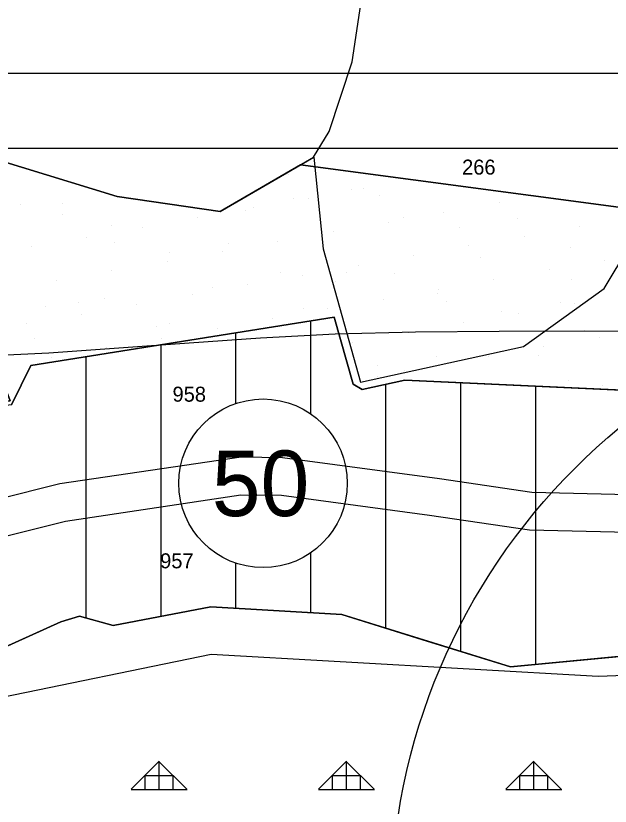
# Model space of a CAD drawing. Extents: x 410727 to 412947, y 4463506 to 4466382.
# Drawn here: x 411205.5 to 411364.1, y 4465781.8 to 4465992.7 of the extents above; entities that cross this region are included whole.
import ezdxf

# ---------------------------------------------------------------- set-up
doc = ezdxf.new("R2010")
doc.units = 0
for name, color, linetype in [('ADAKENARI', 7, 'Continuous'), ('KDS_PARSEL_NO', 7, 'Continuous'), ('KDS_PL', 7, 'Continuous'), ('LJ_ÇERÇEVE', 7, 'Continuous'), ('PL_AYA_ORMAN', 7, 'Continuous'), ('PL_AYA_PARK_DINLENME', 7, 'Continuous'), ('PL_KON_MEV_050', 7, 'Continuous'), ('PL_KON_ONE_50', 7, 'Continuous'), ('sembol', 7, 'Continuous'), ('TR_AZYOGUNLUK_MESKUN', 7, 'Continuous'), ('TR_GELİŞME_KONUT_ÇOKAZ', 7, 'Continuous'), ('TR_ORMAN', 7, 'Continuous'), ('TR_PARKALANI', 7, 'Continuous'), ('Yerlesime_uygunluk_sınırı', 7, 'Continuous')]:
    doc.layers.add(name, color=color, linetype=linetype)

msp = doc.modelspace()

# ---------------------------------------------------------------- linework, layer by layer
at = {"layer": 'ADAKENARI'}
for p, q in [((411209.5, 4465899.44), (411290.5, 4465912.31)), ((411290.5, 4465912.31), (411295.56, 4465894.44)), ((411204.34, 4465888.91), (411209.5, 4465899.44)), ((411295.56, 4465894.44), (411297.94, 4465893)), ((411297.94, 4465893), (411309.34, 4465895.53)), ((411309.34, 4465895.53), (411383, 4465892.12)), ((411231.5, 4465830), (411257.5, 4465834.97)), ((411257.5, 4465834.97), (411292.5, 4465832.97)), ((411188.5, 4465817.97), (411217.5, 4465830.97)), ((411217.5, 4465830.97), (411222.5, 4465832.5)), ((411222.5, 4465832.5), (411231.5, 4465830)), ((411292.5, 4465832.97), (411313.84, 4465826.33)), ((411313.84, 4465826.33), (411337.5, 4465818.97)), ((411337.5, 4465818.97), (411390, 4465824))]:
    msp.add_line(p, q, dxfattribs=at)
for points in [[(411041.23, 4465915.91), (411064.87, 4466022.46), (411117.76, 4466023.84), (411081.79, 4465955.55), (411117.13, 4465936.94), (411082.07, 4465924.54), (411082.97, 4465906.06), (411094.38, 4465893.75), (411095.5, 4465888.94), (411140, 4465889.38), (411204, 4465889.97), (411200.96, 4465897.85), (411190.46, 4465910.39), (411170, 4465921.75), (411155, 4465929), (411125.66, 4465939.96), (411143.96, 4465946.27), (411155.98, 4465967.98), (411178.81, 4465960.97), (411207.01, 4465952.32), (411232.5, 4465944.5), (411260, 4465940.47), (411281.5, 4465952.98), (411373.01, 4465940.76)], [(411373.01, 4465940.76), (411281.5, 4465952.98), (411260, 4465940.47), (411232.5, 4465944.5), (411207.01, 4465952.32), (411178.81, 4465960.97), (411155.98, 4465967.98), (411143.96, 4465946.27), (411125.66, 4465939.96), (411155, 4465929), (411170, 4465921.75), (411190.46, 4465910.39), (411200.96, 4465897.85), (411204, 4465889.97), (411140, 4465889.38), (411095.5, 4465888.94), (411094.38, 4465893.75), (411082.97, 4465906.06), (411082.07, 4465924.54), (411117.13, 4465936.94), (411081.79, 4465955.55), (411117.76, 4466023.84)], [(411383, 4465892.12), (411309.34, 4465895.53), (411297.94, 4465893), (411295.56, 4465894.44), (411290.5, 4465912.31), (411209.5, 4465899.44), (411204.34, 4465888.91)]]:
    msp.add_lwpolyline(points, dxfattribs=at)
at = {"layer": 'KDS_PL'}
for p, q in [((411295.29, 4465980.46), (411299.02, 4466005.3)), ((411289.1, 4465961.88), (411295.29, 4465980.46)), ((411284.98, 4465955), (411289.1, 4465961.88)), ((411178.81, 4465960.97), (411207.01, 4465952.32)), ((411260, 4465940.47), (411285, 4465955)), ((411260, 4465940.47), (411284.98, 4465955)), ((411285, 4465955), (411287.5, 4465930.5)), ((411207.01, 4465952.32), (411232.5, 4465944.5)), ((411232.5, 4465944.5), (411260, 4465940.47)), ((411232.5, 4465944.5), (411260, 4465940.47)), ((411362.5, 4465919.97), (411374.5, 4465940)), ((411287.5, 4465930.5), (411297.5, 4465895)), ((411341, 4465904.47), (411362.5, 4465919.97)), ((411209.5, 4465899.44), (411290.5, 4465912.31)), ((411290.5, 4465912.31), (411295.56, 4465894.44)), ((411297.5, 4465895), (411341, 4465904.47)), ((411204.34, 4465888.91), (411209.5, 4465899.44)), ((411295.56, 4465894.44), (411297.94, 4465893)), ((411297.94, 4465893), (411309.34, 4465895.53)), ((411309.34, 4465895.53), (411383, 4465892.12)), ((411265.62, 4465874.94), (411217.28, 4465867.81)), ((411276.66, 4465874.81), (411265.62, 4465874.94)), ((411318.62, 4465869.19), (411276.66, 4465874.81)), ((411343.25, 4465865.53), (411318.62, 4465869.19)), ((411217.28, 4465867.81), (411192.91, 4465861.72)), ((411218.75, 4465857.88), (411265.53, 4465864.91)), ((411265.53, 4465864.91), (411276.41, 4465864.84)), ((411276.41, 4465864.84), (411315.88, 4465859.44)), ((411401.38, 4465864.16), (411343.25, 4465865.53)), ((411315.88, 4465859.44), (411342.62, 4465855.53)), ((411196.06, 4465852.25), (411218.75, 4465857.88)), ((411342.62, 4465855.53), (411405.75, 4465854.06)), ((411257.5, 4465834.97), (411231.5, 4465830)), ((411292.5, 4465832.97), (411257.5, 4465834.97)), ((411217.5, 4465830.97), (411188.5, 4465817.97)), ((411222.5, 4465832.5), (411217.5, 4465830.97)), ((411231.5, 4465830), (411222.5, 4465832.5)), ((411337.5, 4465818.97), (411292.5, 4465832.97)), ((411390, 4465824), (411337.5, 4465818.97))]:
    msp.add_line(p, q, dxfattribs=at)
at = {"layer": 'LJ_ÇERÇEVE'}
msp.add_circle((411473.17, 4465753.45), 167.6, dxfattribs=at)
at = {"layer": 'PL_AYA_ORMAN'}
msp.add_lwpolyline([(411390, 4465824), (411337.5, 4465818.97), (411313.84, 4465826.33), (411292.5, 4465832.97), (411257.5, 4465834.97), (411231.5, 4465830), (411222.5, 4465832.5), (411217.5, 4465830.97), (411188.5, 4465817.97)], dxfattribs=at)
at = {"layer": 'PL_AYA_PARK_DINLENME'}
for points in [[(411373.01, 4465940.76), (411281.5, 4465952.98), (411260, 4465940.47), (411232.5, 4465944.5), (411207.01, 4465952.32), (411178.81, 4465960.97), (411155.98, 4465967.98), (411143.96, 4465946.27), (411125.66, 4465939.96), (411155, 4465929), (411170, 4465921.75), (411190.46, 4465910.39), (411200.96, 4465897.85), (411204, 4465889.97), (411140, 4465889.38), (411095.5, 4465888.94), (411094.38, 4465893.75), (411082.97, 4465906.06), (411082.07, 4465924.54), (411117.13, 4465936.94), (411081.79, 4465955.55), (411117.76, 4466023.84)], [(411204.34, 4465888.91), (411209.5, 4465899.44), (411290.5, 4465912.31), (411295.56, 4465894.44), (411297.94, 4465893), (411309.34, 4465895.53), (411383, 4465892.12)]]:
    msp.add_lwpolyline(points, dxfattribs=at)
at = {"layer": 'PL_KON_MEV_050'}
for points in [[(411383, 4465892.12), (411309.34, 4465895.53), (411297.94, 4465893), (411295.56, 4465894.44), (411290.5, 4465912.31), (411209.5, 4465899.44), (411204.34, 4465888.91), (411098.59, 4465875.88), (411099.72, 4465871.06), (411101.44, 4465857.22), (411112.42, 4465826.38), (411102.02, 4465825.57), (411084.31, 4465831.87), (411070.45, 4465837.6), (411056.58, 4465843.33), (411042.72, 4465849.06), (411028.86, 4465854.79), (411014.98, 4465860.52), (411001.12, 4465866.25), (410987.26, 4465871.98), (410978.34, 4465875.67), (410974.56, 4465876.98), (410957.12, 4465883.06)], [(411188.5, 4465817.97), (411217.5, 4465830.97), (411222.5, 4465832.5), (411231.5, 4465830), (411257.5, 4465834.97), (411292.5, 4465832.97), (411313.84, 4465826.33), (411337.5, 4465818.97), (411390, 4465824)]]:
    msp.add_lwpolyline(points, dxfattribs=at)
at = {"layer": 'PL_KON_ONE_50'}
msp.add_lwpolyline([(411081.79, 4465955.55), (411117.13, 4465936.94), (411082.07, 4465924.54), (411082.97, 4465906.06), (411094.38, 4465893.75), (411095.5, 4465888.94), (411140, 4465889.38), (411204, 4465889.97), (411200.96, 4465897.85), (411190.46, 4465910.39), (411170, 4465921.75), (411155, 4465929), (411125.66, 4465939.96), (411143.96, 4465946.27), (411155.98, 4465967.98), (411178.81, 4465960.97), (411207.01, 4465952.32), (411232.5, 4465944.5), (411260, 4465940.47), (411281.5, 4465952.98), (411373.01, 4465940.76)], dxfattribs=at)
at = {"layer": 'sembol'}
msp.add_circle((411271.47, 4465867.97), 22.5, dxfattribs=at)
at = {"layer": 'TR_AZYOGUNLUK_MESKUN'}
for p, q in [((411284.26, 4465886.49), (411284.26, 4465911.32)), ((411264.26, 4465889.29), (411264.26, 4465908.14)), ((411244.26, 4465832.44), (411244.26, 4465904.96)), ((411224.26, 4465832.01), (411224.26, 4465901.79)), ((411304.26, 4465829.31), (411304.26, 4465894.4)), ((411324.26, 4465823.09), (411324.26, 4465894.84)), ((411344.26, 4465819.62), (411344.26, 4465893.91)), ((411284.26, 4465833.44), (411284.26, 4465849.46)), ((411264.26, 4465834.58), (411264.26, 4465846.66))]:
    msp.add_line(p, q, dxfattribs=at)
at = {"layer": 'TR_GELİŞME_KONUT_ÇOKAZ'}
for p, q in [((411093.29, 4465977.39), (411432.99, 4465977.39)), ((411190.49, 4465957.39), (411455.67, 4465957.39))]:
    msp.add_line(p, q, dxfattribs=at)
msp.add_lwpolyline([(411191.27, 4466129.24), (411156.49, 4466097.39), (411117.76, 4466023.84), (411081.79, 4465955.55), (411117.13, 4465936.94), (411082.07, 4465924.54), (411082.97, 4465906.06), (411094.38, 4465893.75), (411095.5, 4465888.94), (411140, 4465889.38), (411204, 4465889.97), (411200.96, 4465897.85), (411190.46, 4465910.39), (411170, 4465921.75), (411155, 4465929), (411125.66, 4465939.96), (411143.96, 4465946.27), (411155.98, 4465967.98), (411178.81, 4465960.97), (411207.01, 4465952.32), (411232.5, 4465944.5), (411260, 4465940.47), (411281.5, 4465952.98), (411373.01, 4465940.76)], dxfattribs=at)
at = {"layer": 'TR_ORMAN'}
for p, q in [((411236.24, 4465786.35), (411243.74, 4465793.85)), ((411251.1, 4465786.34), (411243.6, 4465793.84)), ((411243.75, 4465786.29), (411243.75, 4465793.79)), ((411286.24, 4465786.36), (411293.74, 4465793.86)), ((411301.1, 4465786.34), (411293.6, 4465793.84)), ((411293.75, 4465786.29), (411293.75, 4465793.79)), ((411336.24, 4465786.37), (411343.74, 4465793.87)), ((411351.09, 4465786.34), (411343.59, 4465793.84)), ((411343.75, 4465786.29), (411343.75, 4465793.79)), ((411240, 4465790.04), (411247.5, 4465790.04)), ((411240, 4465786.29), (411240, 4465790.04)), ((411247.5, 4465786.29), (411247.5, 4465790.04)), ((411290, 4465790.04), (411297.5, 4465790.04)), ((411290, 4465786.29), (411290, 4465790.04)), ((411297.5, 4465786.29), (411297.5, 4465790.04)), ((411340, 4465790.04), (411347.5, 4465790.04)), ((411340, 4465786.29), (411340, 4465790.04)), ((411347.5, 4465786.29), (411347.5, 4465790.04)), ((411236.25, 4465786.29), (411251.25, 4465786.29)), ((411286.25, 4465786.29), (411301.25, 4465786.29)), ((411336.25, 4465786.29), (411351.25, 4465786.29))]:
    msp.add_line(p, q, dxfattribs=at)
at = {"layer": 'TR_PARKALANI'}
for p, q in [((411278.31, 4465950.38), (411278.31, 4465950.38)), ((411295.19, 4465946.35), (411295.19, 4465946.35)), ((411298.34, 4465946.67), (411298.34, 4465946.67)), ((411298.34, 4465946.67), (411298.34, 4465946.67)), ((411279.55, 4465944.03), (411279.55, 4465944.03)), ((411283.57, 4465944.07), (411283.57, 4465944.07)), ((411283.57, 4465944.07), (411283.57, 4465944.07)), ((411302.65, 4465944.7), (411302.65, 4465944.7)), ((411302.65, 4465944.7), (411302.65, 4465944.7)), ((411334.55, 4465942.9), (411334.55, 4465942.9)), ((411334.55, 4465942.9), (411334.55, 4465942.9)), ((411206.63, 4465942.46), (411206.63, 4465942.46)), ((411217.82, 4465942.63), (411217.82, 4465942.63)), ((411217.82, 4465942.63), (411217.82, 4465942.63)), ((411266.82, 4465940.74), (411266.82, 4465940.74)), ((411266.82, 4465940.74), (411266.82, 4465940.74)), ((411268.8, 4465941.46), (411268.8, 4465941.46)), ((411268.8, 4465941.46), (411268.8, 4465941.46)), ((411217.86, 4465939.68), (411217.86, 4465939.68)), ((411254.03, 4465938.86), (411254.03, 4465938.86)), ((411254.03, 4465938.86), (411254.03, 4465938.86)), ((411309.1, 4465938.82), (411309.1, 4465938.82)), ((411319.77, 4465940.3), (411319.77, 4465940.3)), ((411319.77, 4465940.3), (411319.77, 4465940.3)), ((411339.51, 4465938.54), (411339.51, 4465938.54)), ((411230.98, 4465936.78), (411230.98, 4465936.78)), ((411230.98, 4465936.78), (411230.98, 4465936.78)), ((411305, 4465937.69), (411305, 4465937.69)), ((411305, 4465937.69), (411305, 4465937.69)), ((411355.98, 4465936.53), (411355.98, 4465936.53)), ((411355.98, 4465936.53), (411355.98, 4465936.53)), ((411239.25, 4465936.25), (411239.25, 4465936.25)), ((411239.25, 4465936.25), (411239.25, 4465936.25)), ((411290.23, 4465935.09), (411290.23, 4465935.09)), ((411290.23, 4465935.09), (411290.23, 4465935.09)), ((411323.87, 4465936.22), (411323.87, 4465936.22)), ((411224.48, 4465933.65), (411224.48, 4465933.65)), ((411224.48, 4465933.65), (411224.48, 4465933.65)), ((411231.76, 4465932.15), (411231.76, 4465932.15)), ((411275.46, 4465932.48), (411275.46, 4465932.48)), ((411275.46, 4465932.48), (411275.46, 4465932.48)), ((411341.21, 4465933.92), (411341.21, 4465933.92)), ((411341.21, 4465933.92), (411341.21, 4465933.92)), ((411209.71, 4465931.04), (411209.71, 4465931.04)), ((411209.71, 4465931.04), (411209.71, 4465931.04)), ((411262.18, 4465931.87), (411262.18, 4465931.87)), ((411326.43, 4465931.32), (411326.43, 4465931.32)), ((411326.43, 4465931.32), (411326.43, 4465931.32)), ((411353.41, 4465931.01), (411353.41, 4465931.01)), ((411246.54, 4465929.55), (411246.54, 4465929.55)), ((411260.69, 4465929.88), (411260.69, 4465929.88)), ((411260.69, 4465929.88), (411260.69, 4465929.88)), ((411311.66, 4465928.71), (411311.66, 4465928.71)), ((411311.66, 4465928.71), (411311.66, 4465928.71)), ((411329.6, 4465928.15), (411329.6, 4465928.15)), ((411245.91, 4465927.27), (411245.91, 4465927.27)), ((411245.91, 4465927.27), (411245.91, 4465927.27)), ((411296.89, 4465926.11), (411296.89, 4465926.11)), ((411296.89, 4465926.11), (411296.89, 4465926.11)), ((411362.64, 4465927.55), (411362.64, 4465927.55)), ((411362.64, 4465927.55), (411362.64, 4465927.55)), ((411231.14, 4465924.67), (411231.14, 4465924.67)), ((411231.14, 4465924.67), (411231.14, 4465924.67)), ((411276.08, 4465924.34), (411276.08, 4465924.34)), ((411293.76, 4465924.19), (411293.76, 4465924.19)), ((411306.49, 4465924.05), (411306.49, 4465924.05)), ((411347.87, 4465924.94), (411347.87, 4465924.94)), ((411347.87, 4465924.94), (411347.87, 4465924.94)), ((411216.37, 4465922.06), (411216.37, 4465922.06)), ((411216.37, 4465922.06), (411216.37, 4465922.06)), ((411282.12, 4465923.5), (411282.12, 4465923.5)), ((411282.12, 4465923.5), (411282.12, 4465923.5)), ((411290.85, 4465921.73), (411290.85, 4465921.73)), ((411333.1, 4465922.34), (411333.1, 4465922.34)), ((411333.1, 4465922.34), (411333.1, 4465922.34)), ((411353.94, 4465922.47), (411353.94, 4465922.47)), ((411353.94, 4465922.47), (411353.94, 4465922.47)), ((411257.92, 4465920.22), (411257.92, 4465920.22)), ((411267.35, 4465920.9), (411267.35, 4465920.9)), ((411267.35, 4465920.9), (411267.35, 4465920.9)), ((411318.32, 4465919.73), (411318.32, 4465919.73)), ((411318.32, 4465919.73), (411318.32, 4465919.73)), ((411229.16, 4465917.38), (411229.16, 4465917.38)), ((411252.57, 4465918.29), (411252.57, 4465918.29)), ((411252.57, 4465918.29), (411252.57, 4465918.29)), ((411318.11, 4465918.51), (411318.11, 4465918.51)), ((411318.11, 4465918.51), (411318.11, 4465918.51)), ((411222.09, 4465916.26), (411222.09, 4465916.26)), ((411237.8, 4465915.69), (411237.8, 4465915.69)), ((411237.8, 4465915.69), (411237.8, 4465915.69)), ((411303.55, 4465917.13), (411303.55, 4465917.13)), ((411303.55, 4465917.13), (411303.55, 4465917.13)), ((411320.4, 4465916.52), (411320.4, 4465916.52)), ((411350.81, 4465916.24), (411350.81, 4465916.24)), ((411354.53, 4465915.96), (411354.53, 4465915.96)), ((411354.53, 4465915.96), (411354.53, 4465915.96)), ((411213.52, 4465915.06), (411213.52, 4465915.06)), ((411282.27, 4465914.54), (411282.27, 4465914.54)), ((411282.27, 4465914.54), (411282.27, 4465914.54)), ((411288.78, 4465914.52), (411288.78, 4465914.52)), ((411288.78, 4465914.52), (411288.78, 4465914.52)), ((411335.17, 4465913.92), (411335.17, 4465913.92)), ((411339.76, 4465913.36), (411339.76, 4465913.36)), ((411339.76, 4465913.36), (411339.76, 4465913.36)), ((411223.03, 4465913.08), (411223.03, 4465913.08)), ((411223.03, 4465913.08), (411223.03, 4465913.08)), ((411274.01, 4465911.92), (411274.01, 4465911.92)), ((411274.01, 4465911.92), (411274.01, 4465911.92)), ((411208.26, 4465910.48), (411208.26, 4465910.48)), ((411208.26, 4465910.48), (411208.26, 4465910.48)), ((411243.06, 4465909.85), (411243.06, 4465909.85)), ((411246.43, 4465910.58), (411246.43, 4465910.58)), ((411246.43, 4465910.58), (411246.43, 4465910.58)), ((411259.23, 4465909.31), (411259.23, 4465909.31)), ((411259.23, 4465909.31), (411259.23, 4465909.31)), ((411324.98, 4465910.75), (411324.98, 4465910.75)), ((411324.98, 4465910.75), (411324.98, 4465910.75)), ((411257.84, 4465907.25), (411257.84, 4465907.25)), ((411310.21, 4465908.15), (411310.21, 4465908.15)), ((411310.21, 4465908.15), (411310.21, 4465908.15)), ((411361.19, 4465906.98), (411361.19, 4465906.98)), ((411361.19, 4465906.98), (411361.19, 4465906.98)), ((411210.6, 4465906.62), (411210.6, 4465906.62)), ((411210.6, 4465906.62), (411210.6, 4465906.62)), ((411244.46, 4465906.71), (411244.46, 4465906.71)), ((411244.46, 4465906.71), (411244.46, 4465906.71)), ((411295.44, 4465905.54), (411295.44, 4465905.54)), ((411295.44, 4465905.54), (411295.44, 4465905.54)), ((411229.69, 4465904.11), (411229.69, 4465904.11)), ((411229.69, 4465904.11), (411229.69, 4465904.11)), ((411346.42, 4465904.38), (411346.42, 4465904.38)), ((411346.42, 4465904.38), (411346.42, 4465904.38)), ((411214.92, 4465901.5), (411214.92, 4465901.5)), ((411214.92, 4465901.5), (411214.92, 4465901.5)), ((411317.79, 4465901.75), (411317.79, 4465901.75)), ((411331.64, 4465901.77), (411331.64, 4465901.77)), ((411331.64, 4465901.77), (411331.64, 4465901.77)), ((411345.05, 4465901.95), (411345.05, 4465901.95)), ((411302.15, 4465899.43), (411302.15, 4465899.43)), ((411316.87, 4465899.17), (411316.87, 4465899.17)), ((411316.87, 4465899.17), (411316.87, 4465899.17)), ((411302.1, 4465896.56), (411302.1, 4465896.56)), ((411302.1, 4465896.56), (411302.1, 4465896.56)), ((411309.21, 4465897.99), (411309.21, 4465897.99)), ((411353.08, 4465895.4), (411353.08, 4465895.4)), ((411353.08, 4465895.4), (411353.08, 4465895.4)), ((411362.11, 4465893.94), (411362.11, 4465893.94))]:
    msp.add_line(p, q, dxfattribs=at)
at = {"layer": 'Yerlesime_uygunluk_sınırı'}
for points in [[(411367.59, 4466324.54), (411367.57, 4466324.45), (411365.4, 4466317.37), (411329.85, 4466256.4), (411327.98, 4466256.94), (411298.02, 4466265.64), (411235.39, 4466203.01), (411292.89, 4466117.8), (411249.96, 4466080.27), (411288.76, 4466053.15), (411335.49, 4466003.87), (411401.49, 4466010.55), (411454, 4465988), (411518.19, 4465927.25), (411576.49, 4465880.17), (411546.8, 4465853.02), (411462.76, 4465826.95), (411417.87, 4465818.6), (411360.95, 4465816.44), (411257.66, 4465822.32), (411198.74, 4465810.19), (411081.53, 4465694.24)], [(411380.94, 4465908.37), (411357.39, 4465908.53), (411334.52, 4465908.48), (411312.16, 4465908.28), (411290.71, 4465907.76), (411270.82, 4465906.72), (411251.77, 4465905.4), (411233.02, 4465904.03), (411214.33, 4465902.74), (411195.54, 4465901.81), (411176.52, 4465901.56), (411157.35, 4465901.71), (411138.11, 4465902.09), (411118.79, 4465902.81), (411099.27, 4465904.31), (411079.27, 4465907.24), (411058.94, 4465910.93), (411038.08, 4465914.87), (411015.93, 4465918.8), (410990.34, 4465922.48), (410958.58, 4465925.63), (410923.61, 4465928.48)]]:
    msp.add_lwpolyline(points, dxfattribs=at)

# ---------------------------------------------------------------- texts
at = {"layer": 'KDS_PARSEL_NO'}
for s, p in [('266', (411324.61, 4465950.34)), ('958', (411247.32, 4465889.75)), ('957', (411244.01, 4465845.29))]:
    msp.add_text(s, height=4, dxfattribs=at).set_placement(p)
at = {"layer": 'sembol'}
msp.add_text('50', height=17.5, dxfattribs=at).set_placement((411257.8, 4465859.22))

doc.saveas('drawing.dxf')
